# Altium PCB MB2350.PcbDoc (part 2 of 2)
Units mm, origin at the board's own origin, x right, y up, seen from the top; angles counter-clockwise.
Board outline 43 x 52.78 mm, 4 copper layers (Top Layer, Internal 1, Internal 2, Bottom Layer), stack 1.565 mm thick; 87 components, 78 nets, 331 pads, 863 vias.
Unrouted connection lines stored in the file: 482.
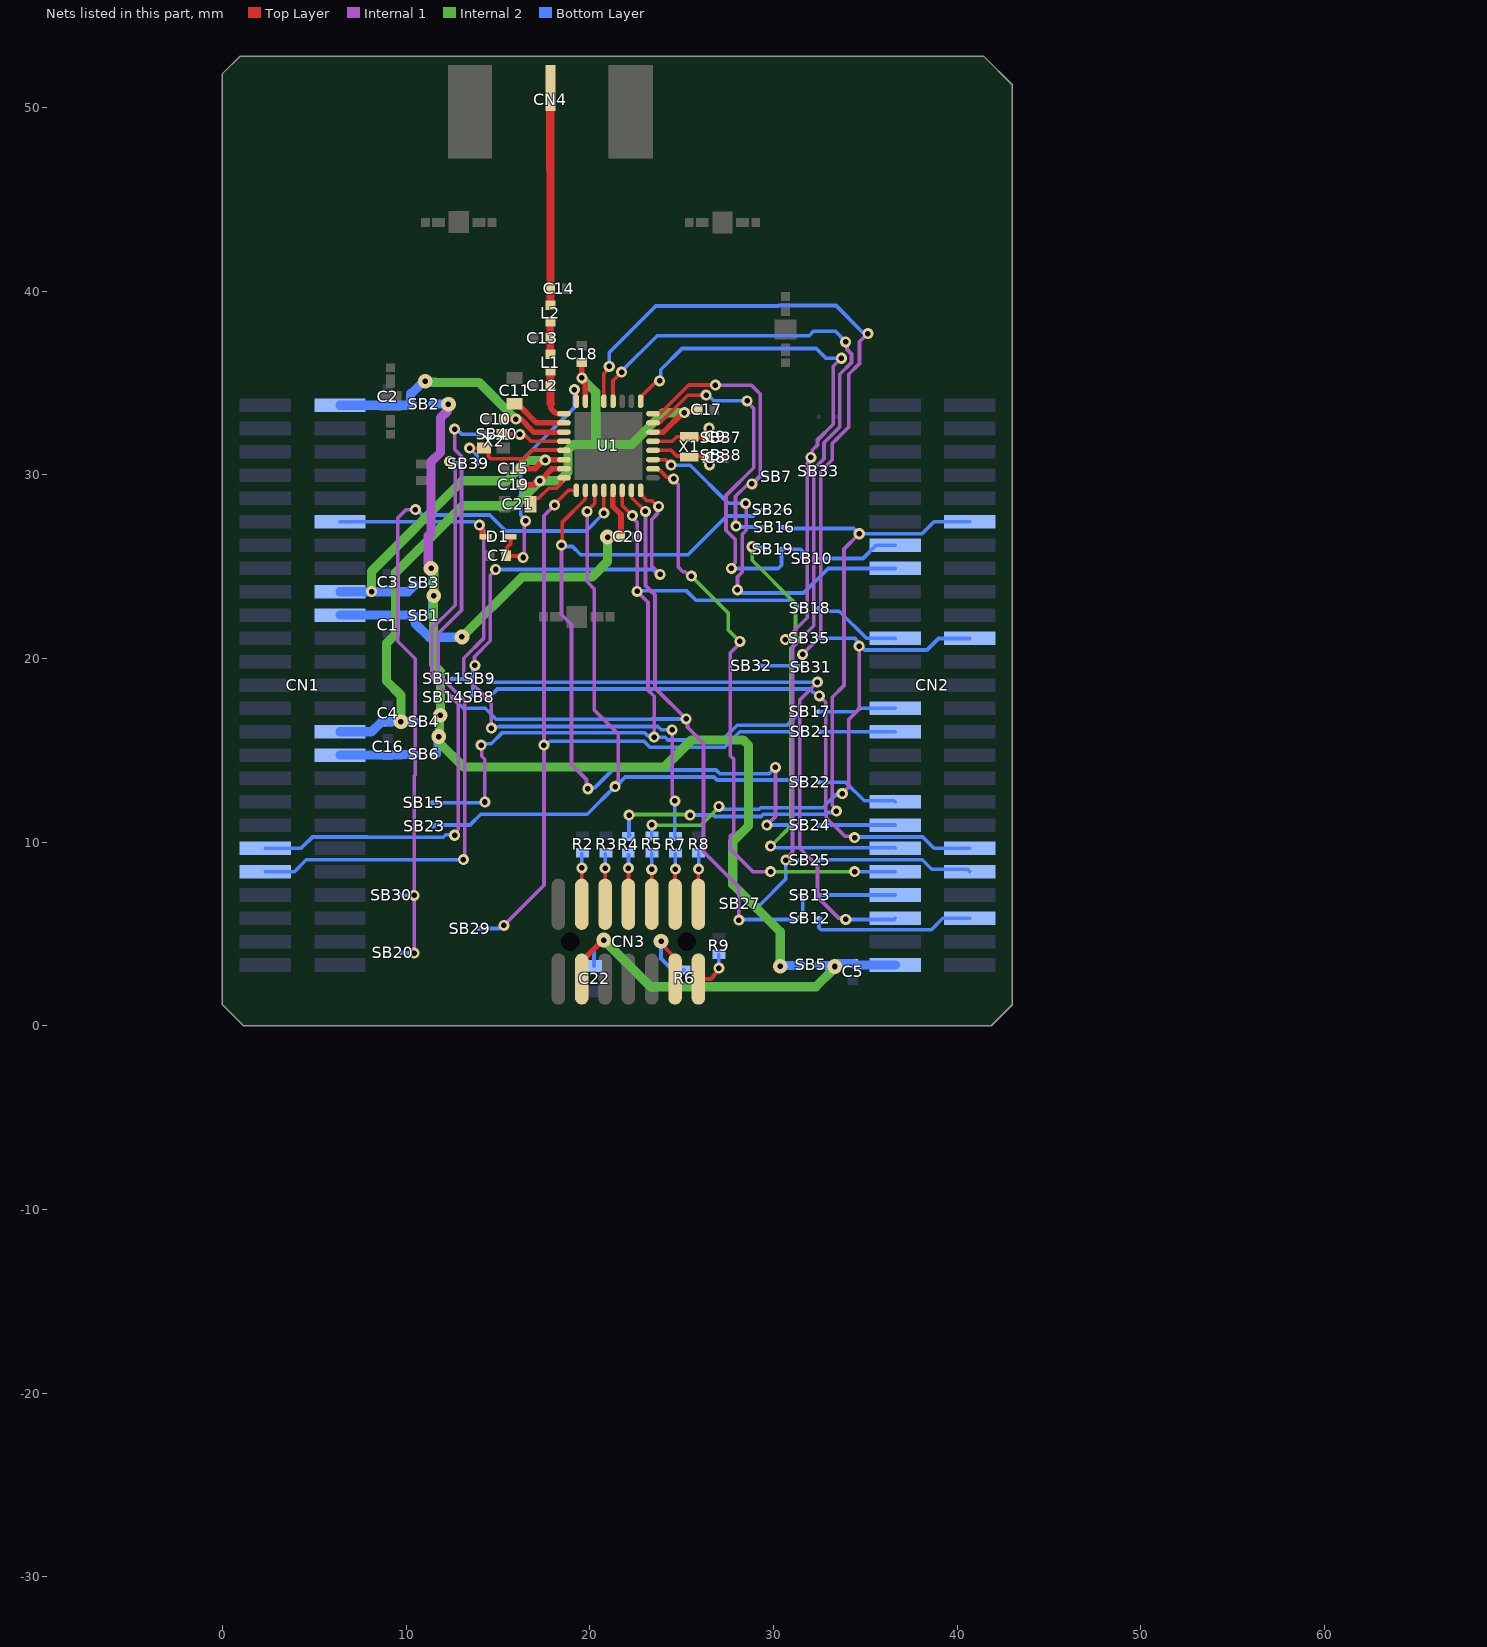
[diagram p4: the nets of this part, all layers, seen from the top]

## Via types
v1: diameter 0.6, hole 0.3, Top Layer to Bottom Layer, tented both sides, 850 vias
v2: diameter 0.8, hole 0.3, Top Layer to Bottom Layer, tented both sides, 13 vias

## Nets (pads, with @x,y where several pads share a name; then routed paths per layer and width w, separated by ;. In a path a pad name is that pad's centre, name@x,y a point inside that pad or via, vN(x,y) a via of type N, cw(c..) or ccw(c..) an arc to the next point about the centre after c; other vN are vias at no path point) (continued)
GPIO32: CN2.12 R4.2 SB16.2 | length 39.1
  Internal 1 w0.2: v1(33.424,11.688) 33.424,11.778 33.193,12.009 33.193,12.871 33.197,12.875 33.197,17.882 33.838,18.523 33.838,25.956 v1(34.669,26.787)
  Internal 2 w0.21: v1(22.136,11.471) 22.158,11.493 25.435,11.493 v1(25.458,11.47)
  Bottom Layer w0.2: R4.2@22.118,10.302 22.187,10.372 22.136,10.423 v1(22.136,11.471) ; v1(25.458,11.47) 26.719,11.47 26.796,11.393 29.326,11.393 29.448,11.516 32.824,11.516 32.919,11.612 33.348,11.612 v1(33.424,11.688) ; SB16.2@30.525,27.141 30.54,27.141 30.608,27.073 34.352,27.073 34.637,26.787 38.092,26.787 38.743,27.438 CN2.12@40.688,27.438
GPIO33: CN2.13 SB10.2 | length 4.4
  Bottom Layer w0.2: SB10.2@32.563,25.439 34.867,25.439 35.596,26.168 CN2.13@36.624,26.168
GPIO34: CN2.15 U1.11 | length 20.2
  Top Layer w0.2: U1.11@23.439,30.825 24.114,30.825 24.418,30.521 v1(24.43,30.521)
  Internal 1 w0.2: v1(28.038,23.726) 28.038,24.451 28.292,24.705 28.292,26.749 28.515,26.972 28.515,28.411 v1(28.486,28.44)
  Bottom Layer w0.2: v1(24.43,30.521) 25.468,30.521 27.55,28.44 v1@28.48,28.44 ; v1(28.038,23.726) 28.146,23.726 28.313,23.559 31.636,23.559 32.975,24.898 CN2.15@36.624,24.898
GPIO37: CN2.21 SB18.1 | length 4.9
  Bottom Layer w0.2: SB18.1@32.45,22.721 32.598,22.573 33.577,22.573 35.045,21.105 36.607,21.105 CN2.21@36.624,21.088
GPIO38: CN2.22 R5.2 SB35.1 | length 29.2
  Internal 1 w0.2: v1(33.743,12.643) 34.101,13.002 34.101,16.675 34.661,17.235 v1(34.661,20.671)
  Internal 2 w0.21: v1(23.381,10.938) 23.404,10.915 26.043,10.915 27.024,11.895 v1(27.024,11.943)
  Bottom Layer w0.2: R5.2@23.376,10.328 v1@23.376,10.938 ; v1(27.024,11.943) 27.132,11.943 27.291,11.784 29.222,11.784 29.303,11.866 32.679,11.866 33.379,12.566 33.666,12.566 v1(33.743,12.643) ; SB35.1@32.431,21.105 34.413,21.105 34.585,20.934 34.585,20.747 v1(34.661,20.671) ; v1@34.588,20.671 34.769,20.671 34.986,20.454 38.351,20.454 38.985,21.088 CN2.22@40.688,21.088
GPIO42: CN2.27 SB17.1 | length 4.1
  Bottom Layer w0.2: SB17.1@32.555,17.102 34.503,17.102 34.679,17.278 CN2.27@36.624,17.278
GPIO44: CN2.29 SB21.2 | length 4
  Bottom Layer w0.2: SB21.2@32.593,16.008 CN2.29@36.624,16.008
GPIO47: CN2.35 SB22.1 | length 4.4
  Bottom Layer w0.2: 32.616,13.264 33.926,13.264 34.941,12.25 36.573,12.25 CN2.35@36.624,12.198
GPIO49: CN2.37 SB24.1 | length 4.2
  Bottom Layer w0.2: SB24.1@32.451,10.916 32.461,10.926 32.811,10.926 32.814,10.928 CN2.37@36.624,10.928
GPIO50: CN2.39 SB19.2 | length 25.6
  Internal 1 w0.2: v1@28.842,25.989 v1(28.842,26.079)
  Internal 2 w0.2: v1(28.842,26.079) 28.842,25.339 31.2,22.981 31.2,20.794 30.948,20.542 30.948,10.879 v1(29.847,9.778)
  Bottom Layer w0.2: v1(28.842,26.079) 28.869,26.052 29.475,26.052 29.475,25.977 SB19.2@29.485,25.977 ; SB19.2@29.52,26.025 SB19.2@29.593,25.952 ; v1(29.847,9.778) 29.956,9.778 30.047,9.687 36.596,9.687 CN2.39@36.624,9.658
GPIO51: CN2.40 SB8.1 | length 33.7
  Internal 1 w0.2: v1(32.498,17.96) 32.843,17.615 32.843,11.492 32.879,11.456 32.879,11.329 33.895,10.313 34.346,10.313 v1(34.422,10.237)
  Bottom Layer w0.2: SB8.1@14.445,17.882 14.455,17.892 14.527,17.892 14.971,18.336 31.948,18.336 32.13,18.153 32.196,18.153 32.389,17.96 v1(32.498,17.96) ; v1(34.422,10.237) 34.463,10.277 38.125,10.277 38.743,9.658 CN2.40@40.688,9.658
GPIO52: CN2.41 U1.10 | length 33
  Top Layer w0.2: U1.10@23.439,30.325 23.691,30.325 23.791,30.225 23.829,30.225 24.199,29.856 24.481,29.856 v1(24.557,29.779)
  Internal 1 w0.2: v1(24.557,29.779) 24.557,29.726 24.821,29.462 24.821,24.969 25.066,24.725 25.177,24.725 25.421,24.481 v1(25.529,24.481) ; v1(28.167,20.926) 28.167,20.818 27.65,20.301 27.65,14.702 27.835,14.517 27.835,10.513 27.65,10.327 27.65,9.623 28.885,8.388 v1(29.847,8.388)
  Internal 2 w0.2: v1(25.529,24.481) 27.528,22.482 27.528,21.565 v1(28.167,20.926) ; v1(29.847,8.388) v1(34.422,8.388)
  Bottom Layer w0.2: v1(34.422,8.388) CN2.41@36.624,8.388
GPIO53: CN2.42 SB25.1 | length 8.4
  Bottom Layer w0.2: 32.592,9.04 38.099,9.04 38.62,8.519 40.557,8.519 CN2.42@40.688,8.388
GPIO54: CN2.43 SB13.1 | length 4.1
  Bottom Layer w0.2: SB13.1@32.563,7.118 CN2.43@36.624,7.118
GPIO55: CN2.45 SB9.1 | length 35.2
  Internal 1 w0.2: v1(32.394,18.703) 31.432,17.741 31.432,9.667 32.394,8.704 32.394,7.015 33.544,5.865 33.857,5.865 v1(33.933,5.788)
  Bottom Layer w0.2: SB9.1@14.486,18.883 14.668,18.701 v1@32.392,18.701 ; v1(33.933,5.788) 36.564,5.788 CN2.45@36.624,5.848
GPIO56: CN2.46 SB12.1 | length 9.1
  Bottom Layer w0.2: SB12.1@32.575,5.848 32.558,5.831 32.558,5.624 32.475,5.542 32.475,5.342 32.593,5.225 38.598,5.225 39.221,5.848 CN2.46@40.688,5.848
NetC7_2: C7.2 D1.1 U1.24 | length 12.8
  Top Layer w0.2: v1(19.164,34.635) 19.164,34.527 19.245,34.446 19.245,34.019 U1.24@19.264,34
  Top Layer w0.21: C7.2@15.489,25.579 16.045,25.579 ; C7.2@15.499,25.588 15.499,26.051 15.675,26.227 D1.1@15.675,26.612
  Internal 1 w0.2: v1(16.371,25.494) 16.435,25.558 16.435,27.427 v1(16.499,27.491)
  Bottom Layer w0.2: v1(16.499,27.491) 16.499,27.544 16.235,27.808 16.235,30.734 19.164,33.663 v1(19.164,34.635)
NetC8_2: C8.2 SB38.1 U1.12 X1.2 | length 3
  Top Layer w0.2: U1.12@23.439,31.325 24.43,31.325 24.738,31.018 25.255,31.018 X1.2@25.343,30.93 ; X1.2@25.343,31.022 26.153,31.022 C8.2@26.212,30.964
  other v1: 26.521,30.542
NetC9_2: C9.2 SB37.1 U1.13 X1.1 | length 3
  Top Layer w0.2: U1.13@23.439,31.825 24.491,31.825 24.734,32.068 X1.1@25.306,32.068 ; X1.1@25.421,32.03 26.291,32.03 26.369,32.108 C9.2@26.374,32.113
  other v1: 26.49,32.531
NetC11_2: C11.2 U1.26 | length 3
  Top Layer w0.3: C11.2@16.057,33.866 17.097,32.825 U1.26@18.589,32.825
NetC12_2: C12.2 L1.1 U1.25 | length 2.7
  Top Layer w0.3: 17.856,33.811 ccw(c18.342,33.811) 18.342,33.325 U1.25@18.589,33.325
  Top Layer w0.4: C12.2@17.823,34.852 C12.2@17.856,34.885
  Top Layer w0.45: L1.1@17.859,35.54 17.859,33.896 17.875,33.881
NetC13_2: C13.2 L1.2 L2.1 | length 1.8
  Top Layer w0.4: L1.2@17.805,36.569 L1.2@17.819,36.556 ; L1.2@17.854,36.556 C13.2@17.854,37.43 L2.1@17.854,38.335
NetC14_2: C14.2 CN4.1 L2.2 | length 11.7
  Top Layer w0.45: C14.2@17.847,40.125 17.854,40.132 17.854,46.604 17.847,46.61 17.847,51.043 CN4.1@17.854,51.05 ; L2.2@17.854,39.236 C14.2@17.854,40.04
NetC21_2: C21.2 U1.32 | length 2.6
  Top Layer w0.2: C21.2@16.767,28.393 16.767,28.508 16.987,28.728 17.221,28.728 17.764,29.271 18.184,29.271 18.433,29.52 18.433,29.779 18.479,29.825 U1.32@18.589,29.825
NetCN3_4: CN3.4 R2.1 | length 2.8
  Top Layer w0.2: CN3.4@19.561,6.614 v1(19.561,8.589) v1@19.561,8.639
  Bottom Layer w0.2: v1(19.561,8.589) R2.1@19.561,9.384
NetCN3_6: CN3.6 R3.1 | length 2.8
  Top Layer w0.2: CN3.6@20.831,6.614 v1(20.831,8.579)
  Bottom Layer w0.2: v1(20.831,8.579) R3.1@20.831,9.372
NetCN3_8: CN3.8 R4.1 | length 2.7
  Top Layer w0.2: CN3.8@22.101,6.614 v1(22.101,8.579)
  Bottom Layer w0.2: v1(22.101,8.579) R4.1@22.101,9.31
NetCN3_10: CN3.10 R5.1 | length 2.8
  Top Layer w0.2: CN3.10@23.371,6.614 v1(23.371,8.519)
  Bottom Layer w0.2: v1(23.371,8.519) R5.1@23.371,9.423
NetCN3_11: CN3.11 R6.2 | length 4.8
  Top Layer w0.2: v2(23.88,4.601) 23.88,4.466 24.641,3.704 CN3.11@24.641,2.544
  Bottom Layer w0.2: v2(23.88,4.601) 23.88,3.661 24.504,3.037 R6.2@25.133,3.037
NetCN3_12: CN3.12 R7.1 | length 2.8
  Top Layer w0.2: CN3.12@24.641,6.614 24.641,8.519 v1(24.651,8.529)
  Bottom Layer w0.2: v1(24.651,8.529) R7.1@24.651,9.396
NetCN3_13: CN3.13 R9.2 | length 2.2
  Top Layer w0.2: CN3.13@25.911,2.544 26.591,2.544 26.733,2.686 26.733,2.734 27.024,3.025 v1(27.024,3.133)
  Bottom Layer w0.2: v1(27.024,3.133) R9.2@27.024,3.9
NetCN3_14: CN3.14 R8.1 | length 2.8
  Top Layer w0.2: CN3.14@25.911,6.614 25.911,8.539 25.921,8.529 v1(25.926,8.529)
  Bottom Layer w0.2: v1(25.926,8.529) R8.1@25.926,9.424
NetSB1_1: SB1.1 SB2.1 SB3.1 SB4.1 SB5.1 SB6.1 | length 55.5
  Internal 1 w0.5: v2(11.355,24.898) 11.355,24.98 11.202,25.133 11.202,26.676 11.355,26.829 11.355,30.699 11.862,31.205 11.862,33.088 12.247,33.474 12.247,33.788 v2(12.305,33.846)
  Internal 2 w0.5: v2(11.355,24.898) 11.355,24.817 11.498,24.674 v2(11.498,23.409) 11.481,23.392 11.481,19.676 11.863,19.294 v2(11.863,16.91) ; v2(11.775,15.748) 11.819,15.792 v2@11.819,16.771 ; v2@11.832,15.388 13.132,14.088 24.064,14.088 25.535,15.56 28.352,15.56 28.645,15.267 28.645,10.893 27.783,10.031 27.783,7.697 30.363,5.117 v2(30.363,3.231)
  Bottom Layer w0.2: 11.7,14.773 11.775,14.848 ; v2@11.7,16.56 11.7,16.665 11.863,16.829 v2(11.863,16.91)
  Bottom Layer w0.4: 11.7,14.773 11.7,15.673 v2(11.775,15.748)
  Bottom Layer w0.5: SB1.1@11.355,22.342 11.441,22.428 11.441,23.352 v2(11.498,23.409) ; SB3.1@11.45,24.106 SB3.1@11.481,24.075 ; SB2.1@11.45,33.846 v2(12.305,33.846) ; SB3.1@11.461,24.106 v2@11.461,24.58 ; v2(30.363,3.231) 30.42,3.289 31.48,3.289 SB5.1@31.5,3.308
NetSB7_1: SB7.1 SB16.1 U1.16 | length 17.2
  Top Layer w0.2: U1.16@23.439,33.325 23.458,33.344 23.842,33.344 24.557,34.059 25.382,34.884 26.836,34.884 v1(26.841,34.879)
  Internal 1 w0.2: v1(26.841,34.879) 28.799,34.879 29.284,34.393 29.284,29.963 v1(28.827,29.505) 28.75,29.429 28.538,29.429 27.936,28.826 27.936,27.228 v1(27.965,27.2)
  Bottom Layer w0.2: v1(27.965,27.2) 28.013,27.151 29.54,27.151 SB16.1@29.55,27.141 ; v1(28.827,29.505) 28.896,29.505 29.337,29.946 29.584,29.946 29.643,29.887 SB7.1@29.657,29.887
NetSB8_2: SB8.2 SB9.2 SB11.2 U1.8 | length 23.2
  Top Layer w0.2: U1.8@22.764,29.15 22.796,29.118 22.796,28.893 23.11,28.579 23.387,28.579 23.689,28.276 v1(23.743,28.276)
  Internal 1 w0.2: v1(13.74,19.625) 13.718,19.647 13.718,20.096 14.582,20.96 14.582,24.524 14.874,24.815 v1(14.874,24.841) ; v1(23.743,28.276) 23.686,28.219 23.686,27.885 23.38,27.579 23.38,25.014 v1(23.823,24.571)
  Bottom Layer w0.2: SB11.2@12.516,18.883 13.072,18.883 SB9.2@13.526,18.883 ; SB8.2@13.47,17.882 13.484,17.882 13.584,17.982 13.631,17.982 13.631,18.783 13.626,18.783 13.579,18.829 SB9.2@13.526,18.883 ; SB9.2@13.511,18.883 SB9.2@13.526,18.883 ; SB9.2@13.632,18.883 13.632,19.409 13.74,19.517 v1(13.74,19.625) ; v1(14.874,24.841) 23.445,24.841 23.715,24.571 v1(23.823,24.571)
NetSB10_1: SB10.1 SB19.1 U1.15 | length 21.3
  Top Layer w0.2: U1.15@23.439,32.825 23.458,32.844 23.837,32.844 25.327,34.334 v1(26.326,34.334)
  Internal 1 w0.2: v1(27.707,24.898) 27.707,25.007 27.912,25.212 27.912,26.474 27.415,26.972 27.415,28.872 28.924,30.381 28.924,33.607 28.564,33.967 v1(28.564,34.027)
  Bottom Layer w0.2: v1(26.326,34.334) 26.434,34.334 26.741,34.027 v1(28.564,34.027) ; v1(27.707,24.898) 30.265,24.898 30.44,25.073 SB19.1@30.44,25.927 ; SB19.1@30.425,25.952 31.454,25.952 31.577,25.828 31.577,25.45 SB10.1@31.588,25.439
NetSB12_2: SB12.2 SB13.2 SB14.2 U1.7 | length 43.9
  Top Layer w0.2: U1.7@22.264,29.15 22.283,29.131 22.283,28.754 v1(23.03,28.007)
  Internal 1 w0.2: v1(23.03,28.007) 23.03,23.972 23.547,23.456 23.547,18.395 25.313,16.628 25.313,16.255 26.187,15.381 26.187,9.476 28.113,7.55 v1(28.113,5.746)
  Bottom Layer w0.2: SB14.2@12.521,17.887 12.97,17.438 12.97,17.428 13.116,17.282 14.308,17.282 14.91,16.679 23.362,16.679 23.388,16.705 v1(25.237,16.705) ; v1(28.113,5.746) 28.153,5.785 31.276,5.785 31.407,5.916 31.42,5.929 31.475,5.984 ; SB13.2@31.588,7.104 31.588,6.097 31.475,5.984 ; SB12.2@31.6,5.848 31.59,5.848 31.475,5.964 31.475,5.984
NetSB15_2: SB15.2 SB17.2 SB18.2 U1.6 | length 48
  Top Layer w0.2: U1.6@21.764,29.15 21.764,28.33 22.312,27.781 v1(22.312,27.772)
  Internal 1 w0.2: v1(14.084,15.274) 14.117,15.241 14.117,14.674 14.28,14.511 v1(14.28,12.182) ; v1(22.312,27.772) 22.312,27.664 22.58,27.396 v1(22.58,23.644) 23.163,23.061 23.163,18.283 23.501,17.946 v1(23.501,15.72)
  Bottom Layer w0.2: SB15.2@11.451,12.15 14.248,12.15 v1(14.28,12.182) ; v1(14.084,15.274) 14.16,15.351 14.627,15.351 15.221,15.945 22.993,15.945 23.141,15.797 23.424,15.797 23.577,15.643 23.634,15.701 24.101,15.701 24.241,15.56 27.224,15.56 28.022,16.358 30.731,16.358 SB17.2@31.475,17.102 ; v1(22.58,23.644) 22.619,23.683 23.933,23.683 23.939,23.677 25.262,23.677 25.763,23.176 31.02,23.176 SB18.2@31.475,22.721
NetSB20_2: SB20.2 SB30.2 U1.4 | length 39.1
  Top Layer w0.2: v1(20.764,27.904) U1.4@20.764,29.15
  Internal 1 w0.2: v1(10.429,3.96) 10.433,3.964 10.433,7.1 v1(10.437,7.104) 10.437,13.61 10.488,13.661 10.488,19.983 9.541,20.93 9.541,27.639 10.005,28.103 v1(10.496,28.103)
  Bottom Layer w0.2: SB30.2@9.683,7.118 9.69,7.111 10.429,7.111 v1(10.437,7.104) ; SB20.2@9.749,3.969 9.753,3.964 10.425,3.964 v1(10.429,3.96) ; v1(10.496,28.103) 10.604,28.103 10.894,27.812 14.557,27.812 15.429,26.941 19.8,26.941 v1(20.764,27.904)
NetSB21_1: SB21.1 SB29.1 U1.1 | length 41.7
  Top Layer w0.2: v1(18.081,28.344) 18.081,28.398 18.834,29.15 U1.1@19.264,29.15
  Internal 1 w0.2: v1(15.319,5.463) 17.501,7.645 v1(17.501,15.274) 17.501,27.764 v1(18.081,28.344)
  Bottom Layer w0.2: SB29.1@13.95,5.293 15.04,5.293 15.211,5.463 v1(15.319,5.463) v1@15.242,5.387 ; v1(17.501,15.274) 17.599,15.274 17.818,15.493 22.95,15.493 23.273,15.17 27.329,15.17 28.167,16.008 SB21.1@31.538,16.008
NetSB22_2: SB22.2 SB23.2 U1.3 | length 38.4
  Top Layer w0.2: v1(19.854,28) 19.854,28.029 20.264,28.439 U1.3@20.264,29.15
  Internal 1 w0.2: v1(19.854,28) 19.854,24.175 20.247,23.782 20.247,17.194 21.551,15.89 21.551,13.393 21.448,13.29 21.448,13.101 v1(21.371,13.025)
  Bottom Layer w0.2: SB23.2@11.491,10.87 11.505,10.87 11.568,10.933 13.474,10.933 14.058,11.516 19.863,11.516 v1(21.371,13.025) 21.419,13.025 21.934,13.539 26.762,13.539 26.923,13.379 31.346,13.379 31.46,13.264 31.641,13.264
NetSB24_2: SB24.2 SB26.2 U1.2 | length 45.7
  Top Layer w0.2: v1(18.457,26.167) 18.507,26.216 18.507,27.431 19.745,28.668 19.745,29.131 U1.2@19.764,29.15
  Internal 1 w0.2: v1(18.457,26.167) 18.457,22.371 18.998,21.83 18.998,14.223 19.818,13.403 19.818,12.98 v1(19.895,12.904) ; v1(29.64,10.929) 30.107,11.397 v1(30.107,14.073)
  Bottom Layer w0.2: v1(18.457,26.167) 18.534,26.09 19.053,26.09 19.504,25.639 25.341,25.639 27.455,27.753 28.888,27.753 29.225,28.09 SB26.2@29.475,28.09 ; v1(19.895,12.904) 19.958,12.967 20.28,12.967 21.237,13.924 26.873,13.924 27.068,13.729 29.763,13.729 v1(30.107,14.073) ; v1(29.64,10.929) 31.447,10.929 31.451,10.926 31.472,10.926 SB24.2@31.476,10.929
NetSB25_2: SB25.2 SB27.2 U1.20 | length 49.6
  Top Layer w0.2: U1.20@21.264,34 21.264,35.114 v1(21.736,35.587)
  Internal 1 w0.2: v1(30.673,9.012) 30.673,9.07 31.03,9.428 31.03,20.624 32.187,21.781 32.187,30.314 32.75,30.877 32.75,31.744 33.608,32.603 33.608,35.473 34.251,36.115 34.251,36.571 34.003,36.819 34.003,37.16 v1(33.926,37.236)
  Bottom Layer w0.2: v1(21.736,35.587) 21.736,35.645 23.664,37.573 31.949,37.573 32.196,37.82 33.366,37.82 33.926,37.259 v1(33.926,37.236) ; SB27.2@28.638,6.648 28.642,6.644 28.842,6.644 28.892,6.595 29.273,6.595 30.673,7.994 v1(30.673,9.012) SB25.2@31.475,9.012 31.618,9.012
NetSB31_1: SB31.1 SB32.1 U1.21 | length 40.4
  Top Layer w0.2: U1.21@20.764,34 20.764,35.504 21.058,35.798 v1(21.058,35.906)
  Internal 1 w0.2: v1@31.58,20.283 v1(31.58,20.221) 32.567,21.207 32.567,30.198 ; 32.571,30.194 33.199,30.822 33.199,31.699 34.096,32.595 34.096,35.465 34.684,36.054 34.684,37.237 v1(35.134,37.687)
  Bottom Layer w0.2: v1(21.058,35.906) 21.058,36.653 23.594,39.19 30.265,39.19 30.286,39.211 33.402,39.211 34.849,37.763 35.057,37.763 v1(35.134,37.687) ; SB32.1@29.269,19.6 31.532,19.6 31.579,19.648 v1@31.579,20.22
NetSB33_2: SB33.2 SB35.2 U1.17 | length 31.2
  Top Layer w0.2: U1.17@22.764,34 22.764,34.225 23.576,35.038 23.721,35.038 v1(23.798,35.114)
  Internal 1 w0.2: v1(30.65,21.022) 31.837,22.209 31.837,30.634 32.038,30.834 v1(32.038,30.942) 32.115,31.019 32.115,31.335 32.4,31.62 32.4,31.889 33.258,32.748 33.258,35.901 v1(33.701,36.343)
  Bottom Layer w0.2: v1@23.8,35.114 v1(23.798,35.114) 23.857,35.174 23.857,35.714 25.015,36.873 32.327,36.873 32.857,36.343 v1(33.701,36.343) ; v1(30.65,21.022) 31.429,21.022 31.603,21.195 ; SB33.2@31.948,30.183 31.948,30.744 32.038,30.834 v1(32.038,30.942)
NetSB39_1: SB39.1 U1.29 X2.1 | length 6.8
  Top Layer w0.2: v1(13.454,31.45) X2.1@14.236,31.45 14.28,31.45 14.48,31.25 14.48,30.995 14.597,30.878 16.426,30.878 16.899,31.351 18.268,31.351 18.274,31.344 18.57,31.344 U1.29@18.589,31.325
  Bottom Layer w0.2: v1(13.454,31.45) 13.874,31.031 SB39.1@13.874,30.591
NetSB40_1: SB40.1 U1.28 X2.3 | length 4.2
  Top Layer w0.2: X2.3@15.286,32.2 15.289,32.198 v1(16.193,32.198) 16.269,32.121 16.498,32.121 16.794,31.825 U1.28@18.589,31.825
  Bottom Layer w0.2: SB40.1@15.424,32.198 v1(16.193,32.198)
NRST: CN1.12 D1.2 R7.2 | length 36.6
  Top Layer w0.254: v1(13.988,27.262) 13.988,27.168 14.127,27.03 14.127,26.635 14.15,26.612 D1.2@14.325,26.612
  Internal 1 w0.2: v1(13.988,27.262) 13.988,27.189 14.232,26.945 14.232,21.105 13.134,20.007 13.134,19.083 14.641,17.576 v1(14.641,16.2) ; v1(24.486,16.11) 24.486,12.488 24.626,12.348 v1(24.626,12.24)
  Bottom Layer w0.2: CN1.12@6.398,27.438 13.704,27.438 13.88,27.262 v1(13.988,27.262) ; v1(14.641,16.2) 14.717,16.276 15.058,16.276 15.076,16.295 23.704,16.295 23.886,16.112 24.484,16.112 v1(24.486,16.11) ; v1(24.626,12.24) 24.626,10.335 R7.2@24.658,10.303
OSC_IN: CN1.39 SB39.2 | length 32.9
  Internal 1 w0.2: v1(12.363,30.717) 12.363,30.609 12.666,30.306 12.666,22.896 11.397,21.627 11.397,18.953 12.832,17.518 12.832,10.672 12.637,10.477 v1(12.637,10.372)
  Bottom Layer w0.2: CN1.39@2.334,9.658 4.279,9.658 4.898,10.277 7.899,10.277 7.916,10.26 12.02,10.26 12.161,10.4 12.609,10.4 v1(12.637,10.372) ; v1(12.363,30.717) 12.44,30.64 12.852,30.64 12.882,30.611 SB39.2@12.896,30.611
OSC_OUT: CN1.41 SB40.2 | length 37.7
  Internal 1 w0.2: v1(12.644,32.482) 12.644,31.372 13.016,31.001 13.016,22.624 11.747,21.355 11.747,19.126 13.192,17.681 13.192,9.358 13.184,9.349 13.184,9.114 v1(13.109,9.04)
  Bottom Layer w0.2: CN1.41@2.334,8.388 3.915,8.388 4.567,9.04 v1(13.109,9.04) ; v1(12.644,32.482) 12.753,32.482 13.037,32.198 SB40.2@14.449,32.198
VDD1: C2.2 C10.1 CN1.2 SB2.2 U1.27 | length 15
  Top Layer w0.3: C10.1@15.307,33.026 v1(15.971,33.026) 16.244,33.026 16.945,32.325 U1.27@18.589,32.325
  Internal 2 w0.5: v2(11.037,35.093) 11.094,35.036 11.603,35.036 11.61,35.028 13.969,35.028 v1(15.971,33.026)
  Bottom Layer w0.5: CN1.2@6.398,33.788 10.181,33.788 10.239,33.846 10.239,34.414 10.276,34.414 10.955,35.093 v2(11.037,35.093) v2@11.118,35.093
VDD3: C3.2 C15.1 CN1.18 SB3.2 U1.30 | length 19.8
  Top Layer w0.3: C15.1@16.276,30.325 17.017,30.325 17.492,30.801 v1(17.573,30.801) ; v1@17.573,30.856 17.605,30.825 U1.30@18.589,30.825
  Internal 2 w0.5: v1(8.116,23.638) 8.116,24.733 13.054,29.671 15.494,29.671 16.605,30.782 17.554,30.782 v1(17.573,30.801)
  Bottom Layer w0.5: CN1.18@6.398,23.628 8.116,23.628 10.108,23.628 SB3.2@10.469,23.989
VDD4: C4.2 C17.1 C18.1 C19.1 CN1.30 SB4.2 U1.14 U1.23 U1.31 | length 44.1
  Top Layer w0.2: v1@25.06,33.376 v1(25.147,33.376)
  Top Layer w0.3: C19.1@16.276,29.464 16.997,29.464 17.204,29.671 v1(17.285,29.671) 17.939,30.325 U1.31@18.589,30.325 ; C18.1@19.563,36.119 19.554,36.11 19.554,35.279 v1(19.561,35.271) 19.561,35.19 19.764,34.988 U1.23@19.764,34 ; U1.14@23.439,32.325 24.009,32.326 v1@25.06,33.376 ; v1(25.147,33.376) 25.205,33.434 25.771,33.434 25.876,33.539 C17.1@25.876,33.544
  Internal 2 w0.5: v2(9.716,16.56) 9.716,17.981 8.935,18.762 8.935,20.824 9.427,21.316 9.427,24.674 13.064,28.312 15.926,28.312 v1(17.285,29.671) 18.345,29.671 18.814,30.14 18.814,31.357 19.107,31.65 22.273,31.65 23.999,33.376 v1(25.147,33.376) ; v1(19.561,35.271) 19.561,35.244 20.318,34.488 20.318,31.975
  Bottom Layer w0.5: CN1.30@6.398,16.008 8.116,16.008 8.662,16.555 ; C4.2@9,16.56 v2(9.716,16.56) SB4.2@10.475,16.56
VDD5: C16.2 CN1.32 SB6.2 | length 4.1
  Bottom Layer w0.5: CN1.32@6.398,14.738 9,14.739 9.715,14.739 9.751,14.773 SB6.2@10.475,14.773
VDD15: C5.2 C22.2 CN2.49 CN3.3 SB5.2 | length 22.7
  Top Layer w0.3: CN3.3@19.561,2.544 19.561,3.516 20.71,4.665 v2(20.764,4.665)
  Internal 2 w0.5: v2(20.764,4.665) 23.305,2.124 32.308,2.124 33.328,3.145 v2(33.328,3.226)
  Bottom Layer w0.2: C22.2@20.231,3.254 20.231,4.132 v2(20.764,4.665)
  Bottom Layer w0.5: SB5.2@32.475,3.308 SB5.2@32.525,3.308 32.545,3.288 33.266,3.288 v2(33.328,3.226) 33.409,3.226 33.566,3.382 34.314,3.382 C5.2@34.319,3.387 34.344,3.387 34.422,3.308 CN2.49@36.624,3.308
VDDA: C1.2 C20.2 CN1.20 SB1.2 U1.5 | length 21.8
  Top Layer w0.2: U1.5@21.251,29.138 U1.5@21.264,29.15
  Top Layer w0.3: U1.5@21.251,29.138 21.251,28.276 21.697,27.831 C20.2@21.697,26.624
  Top Layer w0.5: v2(20.964,26.607) 20.966,26.609 21.646,26.609 21.656,26.619 C20.2@21.656,26.624
  Internal 2 w0.5: v2(13.04,21.171) 13.054,21.171 16.309,24.426 20.115,24.426 20.964,25.275 v2(20.964,26.607)
  Bottom Layer w0.5: CN1.20@6.398,22.358 9,22.358 10.339,22.358 10.505,22.192 ; SB1.2@10.475,22.329 10.475,21.93 11.25,21.155 13.024,21.155 v2(13.04,21.171)
pads on no net: CN1.3 CN1.4 CN1.5 CN1.8 CN1.11 CN1.16 CN1.19 CN1.21 CN1.23 CN1.27 CN1.29 CN1.43 CN1.48 CN1.50 CN2.1 CN2.3 CN2.16 CN2.17 CN2.18 CN2.19 CN2.23 CN2.24 CN2.25 CN2.28 CN2.30 CN2.31 CN2.33 CN2.34 CN2.36 CN2.47 CN2.48 CN3.1 CN3.2 CN3.9 CN3.NPTH1 CN3.NPTH2

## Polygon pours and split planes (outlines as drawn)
GND on Top Layer "GND_L01_P000" (solid, remove dead copper, pour order 0): -1.27,53.848 -1.016,53.594 -1.016,-1.016 44.958,-1.016 44.196,-0.254 44.196,54.356
GND on Internal 1 "GND_L02_P001" (solid, remove dead copper, pour order 1): -1.27,53.848 -1.27,-0.762 -1.016,-1.016 44.577,-1.016 44.577,53.884 44.106,54.355
GND on Internal 2 "GND_L03_P002" (solid, remove dead copper, pour order 2): -1.27,53.848 -1.143,53.721 -1.143,-0.889 44.665,-0.889 44.106,-0.33 44.106,54.355
GND on Bottom Layer "GND_L04_P003" (solid, remove dead copper, pour order 3): -1.27,54.102 -1.27,-0.762 -1.016,-1.016 44.577,-1.016 44.577,53.975 44.196,54.356

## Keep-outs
Top Layer:
  rectangle: 17.64,38.724 18.085,38.837
  rectangle: 17.641,36.045 18.086,36.158
Keep-Out Layer:
  lines w0.1: 1.27,52.779 0.935,52.779 ; 43,1.141 43,47.015 43,48.425 43,50.013 43,51.235 41.456,52.779 0.935,52.779 ; 43.001,1.141 42.504,0.647 41.852,0 1.139,0 0,1.139 0,48.276 0,51.844 0.935,52.779

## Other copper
Top Layer:
  text "1" at 8.901,1.474 h0.9
  text ".Layer_Name" at -19.263,-24.208 h3
  text ".GTL" at 22.432,-24.208 h3
Internal 1:
  pour cut-out: 15.75,52.499 15.75,32.679 15.716,32.645 15.934,32.427 19.807,32.427 19.807,52.51
  text "2" at 9.741,1.47 h0.9
  text ".Layer_Name" at -19.263,-24.208 h3
  text ".G1" at 22.432,-24.208 h3
Internal 2:
  text "3" at 10.785,1.47 h0.9
  text ".Layer_Name" at -19.263,-24.208 h3
  text ".G2" at 22.432,-24.208 h3
Bottom Layer:
  text "4" at 11.661,1.47 h0.9
  text ".GBL" at 11.228,-24.24 h3
  text ".Layer_Name" at 52.542,-24.24 h3
Multi-Layer:
  pour cut-out: 8.2,2.789 8.2,0.989 12.637,0.989 ccw(c12.585,1.042) 12.659,1.042 12.659,2.764

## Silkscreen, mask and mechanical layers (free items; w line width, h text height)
Top Overlay:
  lines w0.05: -0.592,0 1.139,0 ; 0,-0.5 0,1.139
  lines w0.152: 8.812,44.181 14.449,44.181 ; 9.612,43.381 14.437,43.381 ; 19.95,43.381 21.31,43.381 30.312,43.381 ; 19.95,44.181 21.31,44.181 31.112,44.181
  lines w0.2: 8.812,44.181 8.812,21.881 31.112,21.881 31.112,44.181 ; 9.612,43.381 9.612,22.681 30.312,22.681 30.312,43.381
  text "J" at 1.27,48.257 h8
  text "K" at 1.27,43.317 h7.62
  text "MB2350A" at 2.286,3.556 h2.5
  text ".Layer_Name" at -19.263,-24.208 h3
  text ".GTO" at 22.432,-24.208 h3
Bottom Overlay:
  text "I" at 32.738,48.006 h7.62
  text "H" at 40.894,48.006 h7.62
  text "G" at 7.62,47.424 h8
  text ".GBO" at 11.228,-24.24 h3
  text ".Layer_Name" at 52.542,-24.24 h3
Top Paste:
  text ".Layer_Name" at -19.263,-24.208 h3
  text ".GTP" at 22.432,-24.208 h3
Bottom Paste:
  text ".GBP" at 11.228,-24.24 h3
  text ".Layer_Name" at 52.542,-24.24 h3
Top Solder:
  lines w0.1: 30.65,39.491 30.658,39.491
  lines w1: 9.133,22.305 16.121,22.305 ; 9.138,22.305 9.138,31.013 ; 9.165,37.324 9.165,39.742 9.165,43.671 ; 9.165,43.66 9.934,43.66 ; 20.671,43.714 24.159,43.714 ; 22.158,22.306 30.439,22.306 30.65,22.517 ; 30.063,43.755 30.658,43.755 ; 30.65,24.898 30.65,22.517 ; 30.65,30.856 30.658,30.865 ; 30.65,31.371 30.65,22.517 ; 30.65,40.742 30.65,43.714 ; 30.658,31.546 30.658,34.928
  text ".Layer_Name" at -19.263,-24.208 h3
  text ".GTS" at 22.432,-24.208 h3
Bottom Solder:
  text ".GBS" at 11.228,-24.24 h3
  text ".Layer_Name" at 52.542,-24.24 h3
M1-Board Shape:
  lines w0.1: 0,51.844 0,45.75 0,1.139 1.139,0 41.852,0 43.001,1.141 ; 0,51.844 0.935,52.779 41.001,52.779 41.455,52.779 43,51.235 ; 43,1.141 43,45.795 43,51.235
M2-Board Dimensions:
  lines w0.1: -5.613,52.789 0.61,52.789 ; -5.334,0 0.889,0 ; 0,-11.198 0,0.464 ; 43,-10.994 43,0.667
  lines w0.254: -5.786,2.004 -5.131,0 ; -5.504,50.138 -4.826,52.134 ; -5.385,0.001 -4.877,-0.001 ; -5.08,52.136 -4.572,52.133 ; -5.009,20.806 -5.131,0 ; -4.948,31.329 -4.826,52.134 ; -4.453,1.996 -5.131,0 ; -4.171,50.131 -4.826,52.134 ; 0,-11.121 0,-10.613 ; 2,-11.534 0,-10.867 ; 2,-10.201 0,-10.867 ; 17.955,-10.867 0,-10.867 ; 25.045,-10.867 43,-10.867 ; 41,-11.534 43,-10.867 ; 41,-10.201 43,-10.867 ; 43,-11.121 43,-10.613
  text "52.135 (mm)" at -4.167,21.055 h2 r89.66
  text "43 (mm)" at 18.209,-11.708 h2
  text ".Layer_Name" at -19.263,-24.208 h3
  text ".GM2" at 22.432,-24.208 h3
M4-Bottom Dimensions:
  lines w0.1: 4.334,-5.08 4.334,-3 4.334,55.372 ; 38.659,-5 38.659,55.372
  lines w0.254: 4.475,-4.826 4.479,-5.334 ; 6.472,-4.398 4.477,-5.08 ; 6.482,-5.732 4.477,-5.08 ; 16.287,-4.992 4.477,-5.08 ; 26.809,-4.914 38.62,-4.826 ; 36.615,-4.174 38.62,-4.826 ; 36.625,-5.508 38.62,-4.826 ; 38.618,-4.572 38.621,-5.08
  text "CN1/CN2 spacing" at 12.285,-3.435 h2
  text "34.144 (mm)" at 16.548,-5.831 h2 r0.43
Top Assembly:
  text ".Layer_Name" at -19.263,-24.208 h3
  text ".GM14" at 22.432,-24.208 h3
M15-Bottom Assembly:
  text ".GM15" at 11.228,-24.24 h3
  text ".Layer_Name" at 52.542,-24.24 h3
Drill Drawing:
  drawing of 319 lines, arcs and shapes, not listed
  text "Symbol" at -33.042,117.174 h2.16
  text "Count" at -24.58,117.174 h2.16
  text "Hole Size" at -15.8,117.174 h2.16
  text "Plated" at -0.25,117.174 h2.16
  text "Hole Type" at 7.179,117.174 h2.16
  text "Drill Layer Pair" at 17.993,117.174 h2.16
  text "Via/Pad" at 38.492,117.174 h2.16
  text "Pad Shape" at 47.354,117.174 h2.16
  text "Template" at 58.93,117.174 h2.16
  text "Description" at 73.352,117.174 h2.16
  text "Hole Tolerance (+)" at 84.978,117.174 h2.16
  text "Hole Tolerance (-)" at 103.057,117.174 h2.16
  text "Hole Length" at 120.65,117.174 h2.16
  text "Routed Path Length" at 133.026,117.174 h2.16
  text "2" at -24.58,113.445 h1.8
  text "1.00mm (39.37mil)" at -15.8,113.445 h1.8
  text "NPTH" at -0.25,113.445 h1.8
  text "Round" at 7.179,113.445 h1.8
  text "Top Layer - Bottom Layer" at 17.993,113.445 h1.8
  text "Pad" at 38.492,113.445 h1.8
  text "Rounded" at 47.354,113.445 h1.8
  text "c0hn100m105p-1" at 58.93,113.445 h1.8
  text "-" at 120.65,113.445 h1.8
  text "-" at 133.026,113.445 h1.8
  text "863" at -24.58,109.717 h1.8
  text "0.30mm (11.81mil)" at -15.8,109.717 h1.8
  text "PTH" at -0.25,109.717 h1.8
  text "Round" at 7.179,109.717 h1.8
  text "Top Layer - Bottom Layer" at 17.993,109.717 h1.8
  text "Via" at 38.492,109.717 h1.8
  text "Rounded" at 47.354,109.717 h1.8
  text "(Mixed)" at 58.93,109.717 h1.8
  text "-" at 120.65,109.717 h1.8
  text "-" at 133.026,109.717 h1.8
  text "865 Total" at -24.58,105.989 h1.8
  text "Layer" at -23.084,98.552 h1.52
  text "Name" at -12.672,98.552 h1.52
  text "Material" at 10.944,98.552 h1.52
  text "Thickness" at 32.782,98.552 h1.52
  text "Constant" at 49.288,98.552 h1.52
  text "Board Layer Stack" at 63.762,98.552 h1.52
  text "Top Overlay" at -12.672,95.504 h1.52
  text "Top Solder" at -12.672,92.456 h1.52
  text "Solder Resist" at 10.944,92.456 h1.52
  text "0.70mil" at 32.782,92.456 h1.52
  text "4.2" at 49.288,92.456 h1.52
  text "1" at -23.084,89.408 h1.52
  text "Top Layer" at -12.672,89.408 h1.52
  text "1.60mil" at 32.782,89.408 h1.52
  text "Dielectric 1" at -12.672,86.36 h1.52
  text "FR-4" at 10.944,86.36 h1.52
  text "3.00mil" at 32.782,86.36 h1.52
  text "3.7" at 49.288,86.36 h1.52
  text "2" at -23.084,83.312 h1.52
  text "Internal 1" at -12.672,83.312 h1.52
  text "1.20mil" at 32.782,83.312 h1.52
  text "Dielectric 3" at -12.672,80.264 h1.52
  text "50.00mil" at 32.782,80.264 h1.52
  text "4.5" at 49.288,80.264 h1.52
  text "3" at -23.084,77.216 h1.52
  text "Internal 2" at -12.672,77.216 h1.52
  text "1.20mil" at 32.782,77.216 h1.52
  text "Dielectric 2" at -12.672,74.168 h1.52
  text "3.00mil" at 32.782,74.168 h1.52
  text "3.7" at 49.288,74.168 h1.52
  text "4" at -23.084,71.12 h1.52
  text "Bottom Layer" at -12.672,71.12 h1.52
  text "1.60mil" at 32.782,71.12 h1.52
  text "Bottom Solder" at -12.672,68.072 h1.52
  text "Solder Resist" at 10.944,68.072 h1.52
  text "0.70mil" at 32.782,68.072 h1.52
  text "4.2" at 49.288,68.072 h1.52
  text "Bottom Overlay" at -12.672,65.024 h1.52
  text ".Layer_Name" at -19.263,-24.208 h3
  text ".DRL" at 22.432,-24.208 h3
M20-Top Title Box:
  circle w0.254: c58.741,-30.929 r1.3
  region: 58.266,-23.692 42.739,-23.692 42.045,-25.468 40.834,-26.693 39.437,-24.833 39.437,-23.182 40.58,-21.785 42.016,-21.406 58.266,-21.406
  region: 44.263,-32.022 33.507,-32.022 34.5,-29.529 42.358,-29.529 42.807,-28.77 45.015,-31.318
  lines w0.254: 34.5,-29.529 43.292,-29.529 40.226,-25.991 cw(c42.03,-24.047) 42.27,-21.406 59.034,-21.406 58.272,-23.692 ; 37.814,-21.159 cw(c40.24,-22.13) 40.477,-19.527 ; 37.853,-21.127 33.507,-32.022 52.83,-32.022 ccw(c53.078,-29.287) 55.628,-30.307 ; 39.593,-25.061 45.015,-31.318 ; 39.847,-25.061 45.152,-31.183 ; 39.847,-24.807 45.152,-30.929 ; 39.945,-23.692 52.938,-23.692 ; 39.974,-24.68 45.279,-30.802 ; 40.101,-24.553 45.406,-30.675 ; 40.228,-24.426 45.533,-30.548 ; 40.355,-24.299 45.66,-30.421 ; 40.41,-22.347 45.715,-28.468 ; 40.478,-19.527 59.928,-19.527 55.629,-30.305 ; 40.482,-24.172 45.733,-30.231 ; 40.482,-23.918 45.787,-30.04 ; 40.482,-23.664 45.787,-29.786 ; 40.482,-22.775 45.787,-28.897 ; 40.609,-23.537 45.914,-29.659 ; 40.609,-23.156 45.914,-29.278 ; 41.981,-29.542 ccw(c42.086,-29.007) 42.384,-28.55 ; 43.067,-23.679 ccw(c43.041,-24.246) 42.711,-24.708 45.076,-27.437 cw(c43.272,-29.381) 44.005,-31.93 ; 49.349,-31.818 52.238,-23.438 ; 49.571,-31.768 52.44,-23.447 ; 49.698,-31.768 52.567,-23.447 ; 49.952,-31.768 52.821,-23.447 ; 50.206,-31.768 53.075,-23.447 ; 50.46,-31.768 53.329,-23.447 ; 50.714,-31.768 53.583,-23.447 ; 50.968,-31.768 53.837,-23.447 ; 51.222,-31.768 54.091,-23.447 ; 51.476,-31.768 54.345,-23.447 ; 51.685,-31.818 54.574,-23.438 ; 54.574,-23.692 58.266,-23.692 ; 57.598,-23.69 58.36,-21.404 ; 57.764,-23.692 58.526,-21.406 ; 58.018,-23.692 58.78,-21.406
  lines w0.3: -28.263,-30.908 31.737,-30.908 ; -28.263,-25.908 31.737,-25.908 ; -28.263,-20.908 31.737,-20.908 ; 11.737,-35.908 11.737,-20.908 ; 31.737,-35.908 31.737,-15.908 ; 49.349,-31.818 51.685,-31.818 ; -28.263,-35.908 61.737,-35.908 61.737,-15.908 -28.263,-15.908 -28.263,-35.908
  text "Project: '.Board_Name'" at -27.263,-19.124 h3
  text "Layer:" at -27.263,-24.208 h3
  text "Gerber:" at 12.726,-24.208 h3
  text "Variant: '.VariantName'" at -27.263,-29.208 h3
  text "Ref: '.Board_Reference'" at 12.853,-29.208 h3
  text "R" at 58.233,-31.691 h1.52
  text "Date: '.Board_Document_Date'" at -27.263,-34.208 h3
  text "Rev: '.Board_PCB_Revision'" at 12.796,-34.208 h3
M21-Bottom Title Box:
  circle w0.254: c-25.08,-30.929 r1.3
  region: -24.606,-23.692 -9.078,-23.692 -8.384,-25.468 -7.173,-26.693 -5.776,-24.833 -5.776,-23.182 -6.919,-21.785 -8.355,-21.406 -24.606,-21.406
  region: -10.602,-32.022 0.154,-32.022 -0.84,-29.529 -8.697,-29.529 -9.146,-28.77 -11.355,-31.318
  lines w0.254: -25.119,-21.406 -24.357,-23.692 ; -24.865,-21.406 -24.103,-23.692 ; -24.699,-21.404 -23.937,-23.69 ; -24.611,-23.692 -25.373,-21.406 -8.609,-21.406 cw(c-8.369,-24.047) -6.566,-25.991 -9.632,-29.529 -0.84,-29.529 ; -24.606,-23.692 -20.913,-23.692 ; -21.967,-30.307 ccw(c-19.418,-29.287) -19.169,-32.022 0.154,-32.022 -4.193,-21.127 ; -21.968,-30.305 -26.267,-19.527 -6.817,-19.527 ; -20.913,-23.438 -18.024,-31.818 ; -20.685,-23.447 -17.815,-31.768 ; -20.431,-23.447 -17.561,-31.768 ; -20.177,-23.447 -17.307,-31.768 ; -19.923,-23.447 -17.053,-31.768 ; -19.669,-23.447 -16.799,-31.768 ; -19.415,-23.447 -16.545,-31.768 ; -19.277,-23.692 -6.284,-23.692 ; -19.161,-23.447 -16.291,-31.768 ; -18.907,-23.447 -16.037,-31.768 ; -18.78,-23.447 -15.91,-31.768 ; -18.577,-23.438 -15.688,-31.818 ; -12.253,-29.659 -6.948,-23.537 ; -12.253,-29.278 -6.948,-23.156 ; -12.126,-30.04 -6.821,-23.918 ; -12.126,-29.786 -6.821,-23.664 ; -12.126,-28.897 -6.821,-22.775 ; -12.072,-30.231 -6.821,-24.172 ; -12.054,-28.468 -6.749,-22.347 ; -11.999,-30.421 -6.694,-24.299 ; -11.872,-30.548 -6.567,-24.426 ; -11.745,-30.675 -6.44,-24.553 ; -11.618,-30.802 -6.313,-24.68 ; -11.491,-31.183 -6.186,-25.061 ; -11.491,-30.929 -6.186,-24.807 ; -11.355,-31.318 -5.932,-25.061 ; -10.344,-31.93 cw(c-9.611,-29.381) -11.415,-27.437 -9.05,-24.708 ccw(c-9.381,-24.246) -9.407,-23.679 ; -8.723,-28.55 ccw(c-8.425,-29.007) -8.32,-29.542 ; -6.816,-19.527 cw(c-6.58,-22.13) -4.154,-21.159
  lines w0.3: -18.024,-31.818 -15.688,-31.818 ; 1.737,-35.908 1.737,-15.908 ; 1.737,-30.908 61.737,-30.908 ; 1.737,-25.908 61.737,-25.908 ; 1.737,-20.908 61.737,-20.908 ; 21.737,-35.908 21.737,-20.908 ; -28.263,-35.908 61.737,-35.908 61.737,-15.908 -28.263,-15.908 -28.263,-35.908
  text "Project: '.Board_Name'" at 60.543,-19.124 h3
  text "Gerber:" at 20.554,-24.208 h3
  text "Layer:" at 60.542,-24.208 h3
  text "Ref: '.Board_Reference'" at 20.554,-29.208 h3
  text "Variant: '.VariantName'" at 60.543,-29.208 h3
  text "R" at -24.572,-31.691 h1.52
  text "Rev: '.Board_PCB_Revision'" at 20.611,-34.208 h3
  text "Date: '.Board_Document_Date'" at 60.543,-34.208 h3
